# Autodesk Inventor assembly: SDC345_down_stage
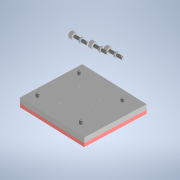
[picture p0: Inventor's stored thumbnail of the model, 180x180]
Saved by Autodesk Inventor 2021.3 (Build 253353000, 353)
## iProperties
Created: 2022-02
Part Number: SDC345_down_stage
Document SubType Name: Assembly
Designer: kengo
Author: kengo
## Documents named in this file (8)
- C:\Users\kengo\Documents\S2S_frame\SDC345\frame_misumi_ver12\stage\SDC345_down_stage.iam
- C:\Users\kengo\Documents\S2S_frame\SDC345\frame_misumi_ver12\stage\SDC3_Delstage.ipt
- C:\Users\kengo\Documents\S2S_frame\SDC345\frame_misumi_ver12\stage\SDC345_Alstage.ipt
- C:\Users\kengo\Documents\S2S_frame\SDC345\frame_misumi_ver12\stage\SCB8-15.ipt
- C:\Users\kengo\Documents\S2S_frame\SDC345\frame_misumi_ver12\stage\SCB8-35.ipt
- C:\Users\kengo\Documents\S2S_frame\SDC345\frame_misumi_ver12\stage\AJSN8-20.ipt
- C:\Users\kengo\Documents\S2S_frame\SDC345\frame_misumi_ver12\stage\SCB6-50.ipt
- C:\Users\kengo\Documents\S2S_frame\SDC345\frame_misumi_ver12\upper-stage\UNST8-40.iam
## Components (18 placed, 7 different names)
1. SDC3_Delstage:1 — メイト:1, フラッシュ:1, フラッシュ:2, リジッド:1, 回転:2, 回転:3, 挿入:1, 挿入:2, 挿入:3
2. SDC345_Alstage:1 — メイト:1, 回転:1, フラッシュ:1, フラッシュ:2, 回転:10
3. SCB8-15:1 — 回転:1
4. SCB8-35:1 — リジッド:1
5. SCB8-35:2 — 回転:2
6. SCB8-35:3 — 回転:3
7. AJSN8-20:1 — 挿入:2, 回転:6, 回転:7
8. AJSN8-20:2 — 挿入:3, 回転:4, 回転:5
9. AJSN8-20:3 — 挿入:1, 回転:8, 回転:9
10. SCB6-50:1 — 回転:4
11. SCB6-50:2 — 回転:5
12. SCB6-50:3 — 回転:6
13. SCB6-50:4 — 回転:7, 回転:10
14. SCB6-50:5 — 回転:8
15. SCB6-50:6 — 回転:9
16. UNST8-40:1 [sub-assembly]
17. UNST8-40:2 [sub-assembly]
18. UNST8-40:3 [sub-assembly]
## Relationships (17: RevoluteJoint 10, Insert 3, Flush 2, Mate 1, WeldJoint 1)
- メイト:1 [Mate]: SDC3_Delstage:1 ↔ SDC345_Alstage:1
- 回転:1 [RevoluteJoint]: SDC345_Alstage:1 ↔ SCB8-15:1
- フラッシュ:1 [Flush]: SDC3_Delstage:1 ↔ SDC345_Alstage:1
- フラッシュ:2 [Flush]: SDC3_Delstage:1 ↔ SDC345_Alstage:1
- リジッド:1 [WeldJoint]: SDC3_Delstage:1 ↔ SCB8-35:1
- 回転:2 [RevoluteJoint]: SDC3_Delstage:1 ↔ SCB8-35:2
- 回転:3 [RevoluteJoint]: SDC3_Delstage:1 ↔ SCB8-35:3
- 挿入:1 [Insert]: SDC3_Delstage:1 ↔ AJSN8-20:3
- 挿入:2 [Insert]: SDC3_Delstage:1 ↔ AJSN8-20:1
- 挿入:3 [Insert]: SDC3_Delstage:1 ↔ AJSN8-20:2
- 回転:4 [RevoluteJoint]: AJSN8-20:2 ↔ SCB6-50:1
- 回転:5 [RevoluteJoint]: AJSN8-20:2 ↔ SCB6-50:2
- 回転:6 [RevoluteJoint]: AJSN8-20:1 ↔ SCB6-50:3
- 回転:7 [RevoluteJoint]: AJSN8-20:1 ↔ SCB6-50:4
- 回転:8 [RevoluteJoint]: AJSN8-20:3 ↔ SCB6-50:5
- 回転:9 [RevoluteJoint]: AJSN8-20:3 ↔ SCB6-50:6
- 回転:10 [RevoluteJoint]: SDC345_Alstage:1 ↔ SCB6-50:4
